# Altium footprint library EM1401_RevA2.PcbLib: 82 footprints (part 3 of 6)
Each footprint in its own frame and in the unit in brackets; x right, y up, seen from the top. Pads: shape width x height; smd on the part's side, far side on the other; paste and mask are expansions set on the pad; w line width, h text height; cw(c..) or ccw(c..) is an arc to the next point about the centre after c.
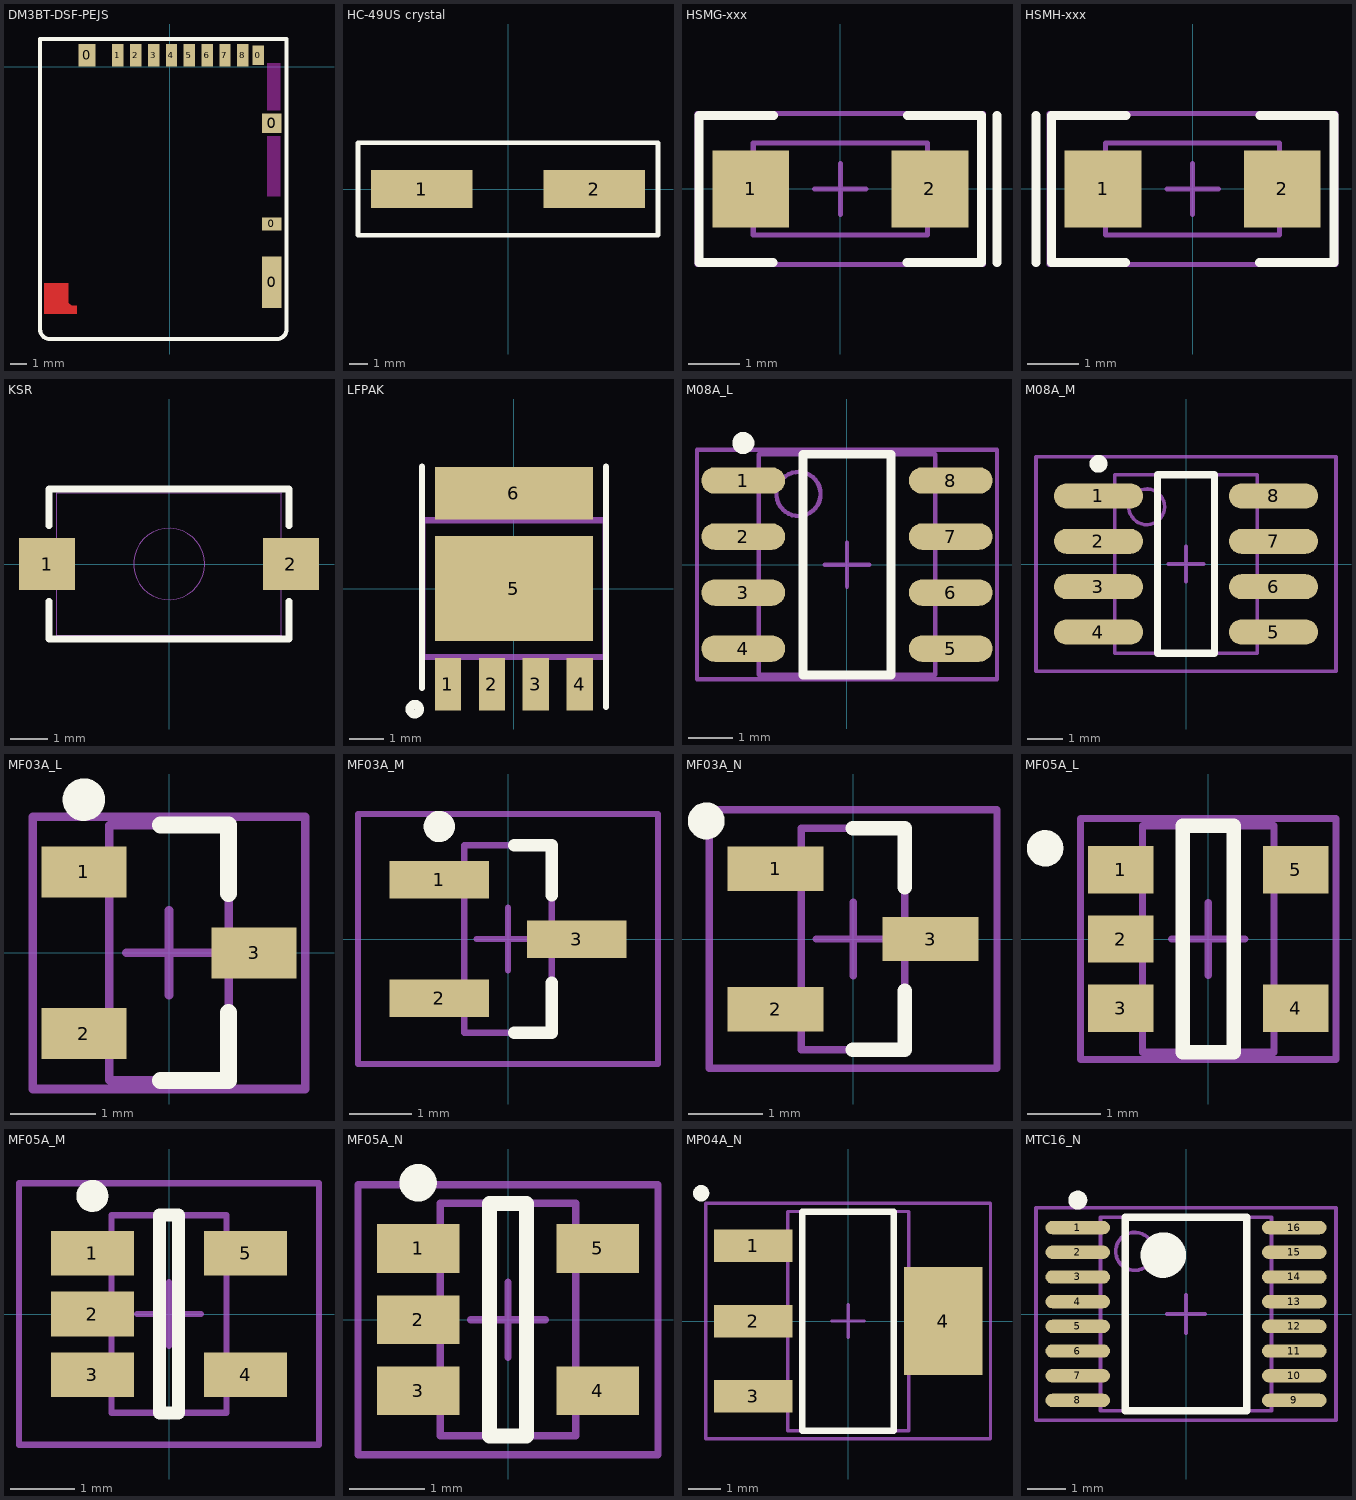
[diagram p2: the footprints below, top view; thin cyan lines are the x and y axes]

## DM3BT-DSF-PEJS [mm] "Hirose DM3 series microSD card connector"
height 1.68
pads (13):
  rect 1.05x1.4 smd: 0(-5.1,0.7)
  rect 0.7x1.2 smd: 0(5.45,0.7)
  rect 1.2x3.2 smd: 0(6.3,-13.3)
  rect 1.2x0.8 smd: 0(6.3,-9.7)
  rect 1.2x1.2 smd: 0(6.3,-3.5)
  rect 0.7x1.4 smd: 1(-3.2,0.7) 2(-2.1,0.7) 3(-1,0.7) 4(0.1,0.7) 5(1.2,0.7) 6(2.3,0.7) 7(3.4,0.7) 8(4.5,0.7)
Top Layer:
  region: -6.05,-14.75 -5.75,-14.75 -5.75,-15.25 -7.75,-15.25 -7.75,-13.35 -6.25,-13.35 -6.25,-14.55
Top Overlay:
  lines w0.254: -8,-16.2 ccw(c-7.4,-16.2) -7.4,-16.8 6.6,-16.8 ccw(c6.6,-16.2) 7.2,-16.2 7.2,1.7 -8,1.7 -8,-16.2
Keep-Out Layer:
  region: 6,-2.7 6,0.2 6.8,0.2 6.8,-2.7
  region: 6,-8 6,-4.3 6.8,-4.3 6.8,-8

## HC-49US crystal [mil]
pads (2):
  rect 220x83 smd: 1(-187,0) 2(187,0)
Top Overlay:
  lines w10: -325,-100 325,-100 325,100 -325,100 -325,-100

## HSMG-xxx [mm]
pads (2):
  rect 1.5x1.5 smd: 1(-1.75,0) 2(1.75,0)
Top Overlay:
  lines w0.178: -2.758,-1.43 -2.753,-1.435 ; -1.313,-1.435 -2.758,-1.435 -2.758,1.435 -1.303,1.435 ; 1.306,-1.435 2.761,-1.435 2.761,1.435 1.316,1.435 ; 2.756,1.435 2.761,1.43 ; 3.061,-1.435 3.061,1.435
Mechanical 5:
  text ".designator" at -1.844,-0.584 h1.02
Mechanical 13:
  lines w0.1: -1.7,-0.9 1.7,-0.9 1.7,0.9 -1.7,0.9 -1.7,-0.9
Mechanical 15:
  lines w0.1: -0.5,0 0.5,0 ; 0,-0.5 0,0.5 ; -2.8,-1.475 -2.8,1.475 2.8,1.475 2.8,-1.475 -2.8,-1.475
3D body: height 1.35, standoff 0, extent -1.7,-0.9 1.7,0.9

## HSMH-xxx [mm]
pads (2):
  rect 1.5x1.5 smd: 1(-1.75,0) 2(1.75,0)
Top Overlay:
  lines w0.178: -3.058,-1.435 -3.058,1.435 ; -2.758,-1.43 -2.753,-1.435 ; -1.313,-1.435 -2.758,-1.435 -2.758,1.435 -1.303,1.435 ; 1.306,-1.435 2.761,-1.435 2.761,1.435 1.316,1.435 ; 2.756,1.435 2.761,1.43
Mechanical 5:
  text ".designator" at -1.844,-0.584 h1.02
Mechanical 13:
  lines w0.1: -1.7,-0.9 1.7,-0.9 1.7,0.9 -1.7,0.9 -1.7,-0.9
Mechanical 15:
  lines w0.1: -0.5,0 0.5,0 ; 0,-0.5 0,0.5 ; -2.8,-1.475 -2.8,1.475 2.8,1.475 2.8,-1.475 -2.8,-1.475
3D body: height 1.35, standoff 0, extent -1.7,-0.9 1.7,0.9

## KSR [mm] "C&K Components SPST switch"
height 2.65
pads (2):
  rect 1.5x1.4 smd: 1(-3.25,0) 2(3.25,0)
Top Overlay:
  lines w0.178: -3.2,-0.998 -3.2,-2 3.2,-2 3.2,-0.998 ; -3.2,1.016 -3.2,2 3.2,2 3.2,1.016
Mechanical 5:
  text ".Designator" at -0.824,-0.432 h1.02
Mechanical 13:
  circle w0.01: c0,0 r0.95
  lines w0.001: -3,-1.9 -3,0 -3,1.9 0,1.9 3,1.9 3,0 3,-1.9 0,-1.9 -3,-1.9
3D body: height 1.8, standoff 0, extent -3.001,-1.901 3.001,1.901
3D body: height 2.65, standoff 1.8, extent -0.958,-0.958 0.958,0.958

## LFPAK [mm] "Renesas LFPAK recommended land pattern  2008-05-26, page 17 of REJ11K0001_surface.pdf"
height 1.1
pads (6):
  rect 0.76x1.52 smd: 1(-1.905,-2.76) 2(-0.635,-2.76) 3(0.635,-2.76) 4(1.905,-2.76)
  rect 4.57x3.04 smd: 5(0,0)
  rect 4.57x1.52 smd: 6(0,2.76)
Top Overlay:
  circle w0.254: c-2.865,-3.485 r0.141
  lines w0.178: -2.66,-2.868 -2.66,3.52 ; 2.66,-3.421 2.66,3.52
Mechanical 5:
  text ".Designator" at -1.524,-0.508 h1.02
Mechanical 13:
  circle w0.178: c-1.6,-0.025 r0.478
  lines w0.178: -2.65,-1.975 2.65,-1.975 2.65,1.975 -2.65,1.975 -2.65,-1.975
3D body: height 1.1, standoff 0, extent -2.649,-1.974 2.649,1.974
3D body: height 1.1, standoff 1.1, extent -2.086,-0.511 -1.114,0.461

## M08A_L [mm] "SOIC, 8-Leads, Body 4.9x3.9mm, Pitch 1.27mm, IPC High Density"
height 1.75
pads (8):
  oval 1.9x0.6 smd: 1(-2.35,1.905) 2(-2.35,0.635) 3(-2.35,-0.635) 4(-2.35,-1.905) 5(2.35,-1.905) 6(2.35,-0.635) 7(2.35,0.635) 8(2.35,1.905)
Top Overlay:
  circle w0.25: c-2.35,2.755 r0.125
  lines w0.2: -1,-2.5 1,-2.5 1,2.5 -1,2.5 -1,-2.5
Mechanical 5:
  text ".Designator" at -0.024,-0.008 h1.02
Mechanical 13:
  circle w0.1: c-1.1,1.6 r0.5
  lines w0.1: -2,-2.5 2,-2.5 2,2.5 -2,2.5 -2,-2.5
Mechanical 15:
  lines w0.1: -0.5,0 0.5,0 ; 0,-0.5 0,0.5 ; -3.4,-2.6 3.4,-2.6 3.4,2.6 -3.4,2.6 -3.4,-2.6
3D body: height 1.75, standoff 0, extent -2,-2.5 2,2.5

## M08A_M [mm] "SOIC, 8-Leads, Body 4.9x3.9mm, Pitch 1.27mm, IPC Low Density"
height 1.75
pads (8):
  oval 2.5x0.7 smd: 1(-2.45,1.905) 2(-2.45,0.635) 3(-2.45,-0.635) 4(-2.45,-1.905) 5(2.45,-1.905) 6(2.45,-0.635) 7(2.45,0.635) 8(2.45,1.905)
Top Overlay:
  circle w0.25: c-2.45,2.805 r0.125
  lines w0.2: -0.8,-2.5 0.8,-2.5 0.8,2.5 -0.8,2.5 -0.8,-2.5
Mechanical 5:
  text ".Designator" at -1.524,-0.508 h1.02
Mechanical 13:
  circle w0.1: c-1.1,1.6 r0.5
  lines w0.1: -2,-2.5 2,-2.5 2,2.5 -2,2.5 -2,-2.5
Mechanical 15:
  lines w0.1: -0.5,0 0.5,0 ; 0,-0.5 0,0.5 ; -4.2,-3 4.2,-3 4.2,3 -4.2,3 -4.2,-3
3D body: height 1.75, standoff 0, extent -2,-2.5 2,2.5

## MF03A_L [mm] "SOT23, 3-Leads, Body 2.9x1.3mm, Pitch 0.95mm, Lead Span 2.4mm, IPC High Density"
height 1.12
pads (3):
  rect 1x0.6 smd: 1(-1,0.95) 2(-1,-0.95) 3(1,0)
Top Overlay:
  circle w0.25: c-1,1.8 r0.125
  lines w0.2: -0.1,-1.5 0.7,-1.5 0.7,-0.7 ; -0.1,1.5 0.7,1.5 0.7,0.7
Mechanical 5:
  text ".Designator" at -1.524,-0.508 h1.02
Mechanical 13:
  lines w0.1: -0.7,-1.5 -0.7,1.5 0.7,1.5 0.7,-1.5 -0.7,-1.5
Mechanical 15:
  lines w0.1: -0.5,0 0.5,0 ; 0,-0.5 0,0.5 ; -1.6,-1.6 -1.6,1.6 1.6,1.6 1.6,-1.6 -1.6,-1.6
3D body: height 1.12, standoff 0, extent -0.7,-1.5 0.7,1.5

## MF03A_M [mm] "SOT23, 3-Leads, Body 2.9x1.3mm, Pitch 0.95mm, Lead Span 2.4mm, IPC Low Density"
height 1.12
pads (3):
  rect 1.6x0.6 smd: 1(-1.1,0.95) 2(-1.1,-0.95) 3(1.1,0)
Top Overlay:
  circle w0.25: c-1.1,1.8 r0.125
  lines w0.2: 0.1,-1.5 0.7,-1.5 0.7,-0.7 ; 0.1,1.5 0.7,1.5 0.7,0.7
Mechanical 5:
  text ".Designator" at -1.524,-0.508 h1.02
Mechanical 13:
  lines w0.1: -0.7,-1.5 -0.7,1.5 0.7,1.5 0.7,-1.5 -0.7,-1.5
Mechanical 15:
  lines w0.1: -0.5,0 0.5,0 ; 0,-0.5 0,0.5 ; -2.4,-2 -2.4,2 2.4,2 2.4,-2 -2.4,-2
3D body: height 1.12, standoff 0, extent -0.7,-1.5 0.7,1.5

## MF03A_N [mm] "SOT23, 3-Leads, Body 2.9x1.3mm, Pitch 0.95mm, Lead Span 2.4mm, IPC Medium Density"
height 1.12
pads (3):
  rect 1.3x0.6 smd: 1(-1.05,0.95) 2(-1.05,-0.95) 3(1.05,0)
Top Overlay:
  circle w0.25: c-1.989,1.6 r0.125
  lines w0.2: 0,-1.5 0.7,-1.5 0.7,-0.7 ; 0,1.5 0.7,1.5 0.7,0.7
Mechanical 5:
  text ".Designator" at -1.524,-0.508 h1.02
Mechanical 13:
  lines w0.1: -0.7,-1.5 0.7,-1.5 0.7,1.5 -0.7,1.5 -0.7,-1.5
Mechanical 15:
  lines w0.1: -0.5,0 0.5,0 ; 0,-0.5 0,0.5 ; -1.95,-1.75 -1.95,1.75 1.95,1.75 1.95,-1.75 -1.95,-1.75
3D body: height 1.12, standoff 0, extent -0.7,-1.5 0.7,1.5

## MF05A_L [mm] "SOT23, 5-Leads, Body 2.9x1.6mm, Pitch 0.95mm, Lead Span 2.8mm, IPC High Density"
height 1.22
pads (5):
  rect 0.9x0.65 smd: 1(-1.2,0.95) 2(-1.2,0) 3(-1.2,-0.95) 4(1.2,-0.95) 5(1.2,0.95)
Top Overlay:
  circle w0.25: c-2.235,1.243 r0.125
  lines w0.2: -0.35,-1.55 0.35,-1.55 0.35,1.55 -0.35,1.55 -0.35,-1.55
Mechanical 5:
  text ".designator" at 0.315,-1.63 h1.02
Mechanical 13:
  lines w0.1: -0.9,-1.55 0.9,-1.55 0.9,1.55 -0.9,1.55 -0.9,-1.55
Mechanical 15:
  lines w0.1: -0.5,0 0.5,0 ; 0,-0.5 0,0.5 ; -1.75,-1.65 1.75,-1.65 1.75,1.65 -1.75,1.65 -1.75,-1.65
3D body: height 1.22, standoff 0, extent -0.9,-1.55 0.9,1.55

## MF05A_M [mm] "SOT23, 5-Leads, Body 2.9x1.6mm, Pitch 0.95mm, Lead Span 2.8mm, IPC Low Density"
height 1.22
pads (5):
  rect 1.3x0.7 smd: 1(-1.2,0.95) 2(-1.2,0) 3(-1.2,-0.95) 4(1.2,-0.95) 5(1.2,0.95)
Top Overlay:
  circle w0.25: c-1.2,1.85 r0.125
  lines w0.2: -0.15,-1.55 0.15,-1.55 0.15,1.55 -0.15,1.55 -0.15,-1.55
Mechanical 5:
  text ".designator" at 0.5,-2.5 h1.02
Mechanical 13:
  lines w0.1: -0.9,-1.55 -0.9,1.55 0.9,1.55 0.9,-1.55 -0.9,-1.55
Mechanical 15:
  lines w0.1: -0.5,0 0.5,0 ; 0,-0.5 0,0.5 ; -2.35,-2.05 -2.35,2.05 2.35,2.05 2.35,-2.05 -2.35,-2.05
3D body: height 1.22, standoff 0, extent -0.9,-1.55 0.9,1.55

## MF05A_N [mm] "SOT23, 5-Leads, Body 2.9x1.6mm, Pitch 0.95mm, Lead Span 2.8mm, IPC Medium Density"
height 1.19
pads (5):
  rect 1.1x0.65 smd: 1(-1.2,0.95) 2(-1.2,0) 3(-1.2,-0.95) 4(1.2,-0.95) 5(1.2,0.95)
Top Overlay:
  circle w0.25: c-1.2,1.825 r0.125
  lines w0.2: -0.25,-1.55 0.25,-1.55 0.25,1.55 -0.25,1.55 -0.25,-1.55
Mechanical 5:
  text ".Designator" at -1.524,-0.508 h1.02
Mechanical 13:
  lines w0.1: -0.9,-1.55 0.9,-1.55 0.9,1.55 -0.9,1.55 -0.9,-1.55
Mechanical 15:
  lines w0.1: -0.5,0 0.5,0 ; 0,-0.5 0,0.5 ; -2,-1.8 2,-1.8 2,1.8 -2,1.8 -2,-1.8
3D body: height 1.19, standoff 0, extent -0.9,-1.55 0.9,1.55

## MP04A_N [mm] "SOT223, 4-Leads, Body 6.5x3.5mm, Pitch 2.3mm, Lead Span 7mm, IPC Medium Density"
height 1.8
pads (4):
  rect 2.4x1 smd: 1(-2.9,2.3) 2(-2.9,0) 3(-2.9,-2.3)
  rect 2.4x3.3 smd: 4(2.9,0)
Top Overlay:
  circle w0.25: c-4.496,3.91 r0.125
  lines w0.2: -1.4,-3.35 1.4,-3.35 1.4,3.35 -1.4,3.35 -1.4,-3.35
Mechanical 5:
  text ".Designator" at 0.508,-3.024 h1.02
Mechanical 13:
  lines w0.1: -1.85,-3.35 -1.85,3.35 1.85,3.35 1.85,-3.35 -1.85,-3.35
Mechanical 15:
  lines w0.1: -0.5,0 0.5,0 ; 0,-0.5 0,0.5 ; -4.35,-3.6 4.35,-3.6 4.35,3.6 -4.35,3.6 -4.35,-3.6
3D body: height 1.8, standoff 0, extent -1.85,-3.35 1.85,3.35

## MTC16_N [mm] "TSOP, 16-Leads, Body 5x4.4mm, Pitch 0.65mm, IPC Medium Density"
height 1.1
pads (16):
  oval 1.7x0.35 smd: 1(-2.85,2.275) 2(-2.85,1.625) 3(-2.85,0.975) 4(-2.85,0.325) 5(-2.85,-0.325) 6(-2.85,-0.975) 7(-2.85,-1.625) 8(-2.85,-2.275) 9(2.85,-2.275) 10(2.85,-1.625) 11(2.85,-0.975) 12(2.85,-0.325) 13(2.85,0.325) 14(2.85,0.975) 15(2.85,1.625) 16(2.85,2.275)
Top Overlay:
  circle w0.25: c-2.85,3 r0.125
  circle w0.6: c-0.6,1.55 r0.3
  lines w0.2: -1.6,-2.55 -1.6,2.55 1.6,2.55 1.6,-2.55 -1.6,-2.55
Mechanical 5:
  text ".designator" at 0.465,-2.08 h1.02
Mechanical 13:
  circle w0.1: c-1.35,1.65 r0.5
  lines w0.1: -2.25,-2.55 -2.25,2.55 2.25,2.55 2.25,-2.55 -2.25,-2.55
Mechanical 15:
  lines w0.1: -0.5,0 0.5,0 ; 0,-0.5 0,0.5 ; -3.95,-2.8 -3.95,2.8 3.95,2.8 3.95,-2.8 -3.95,-2.8
3D body: height 1.1, standoff 0, extent -2.25,-2.55 2.25,2.55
